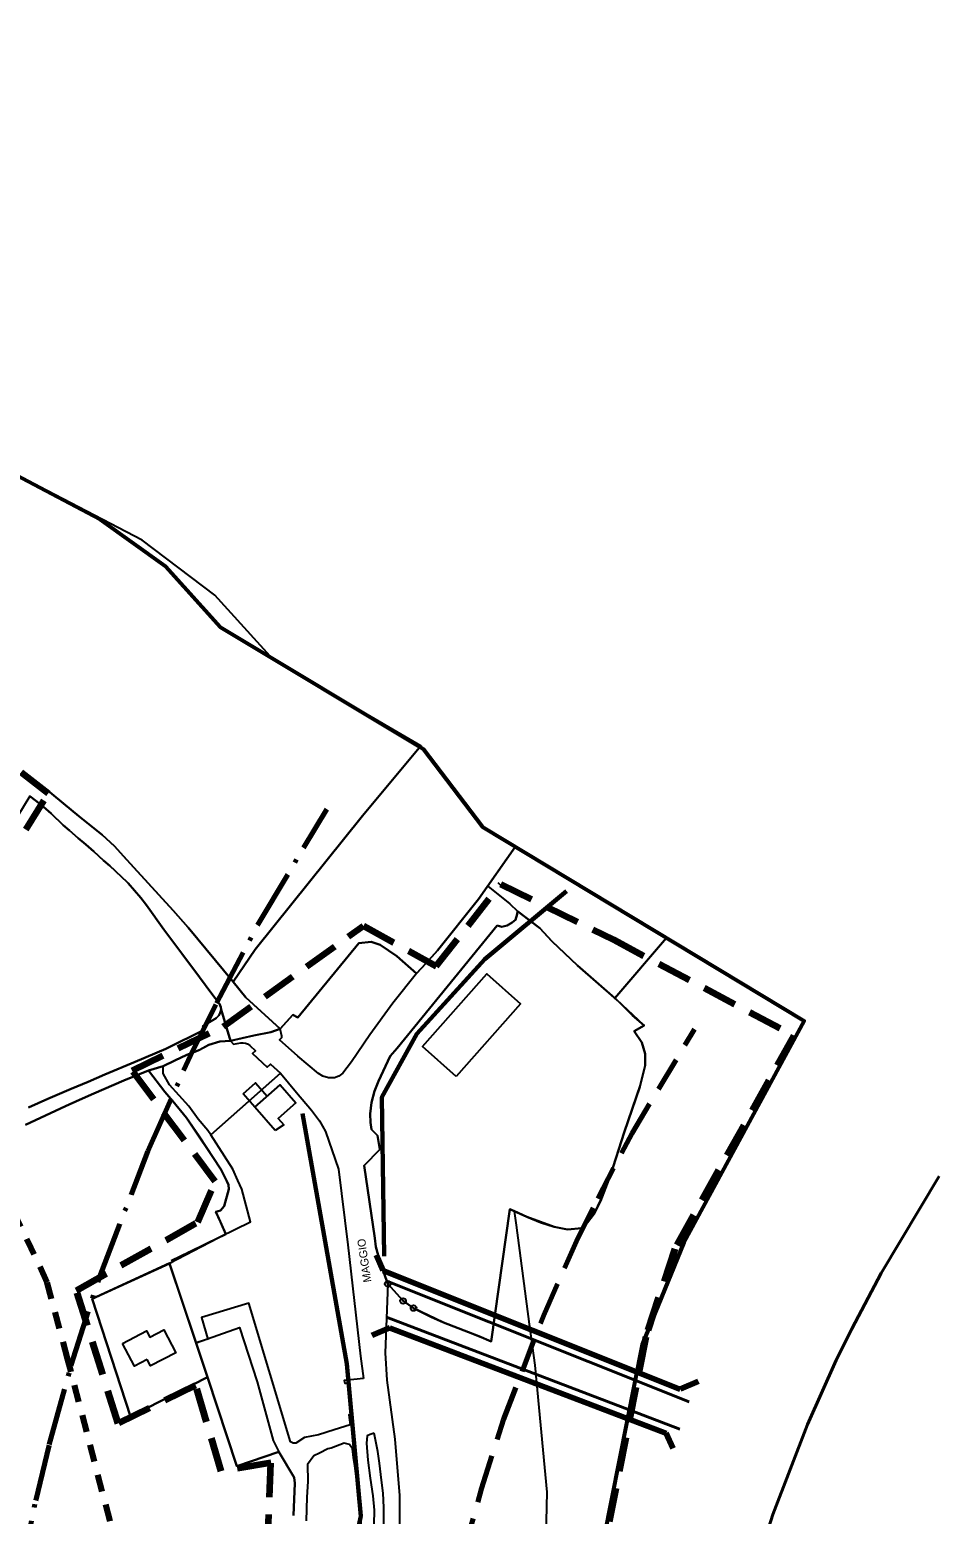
# Model space of a CAD drawing. Extents: x 654952 to 658955, y 890426 to 894481.
# Drawn here: x 658129 to 658448, y 893668 to 894188 of the extents above; entities that cross this region are included whole.
import ezdxf

# ---------------------------------------------------------------- set-up
doc = ezdxf.new("R2010")
doc.units = 0
doc.header["$LTSCALE"] = 4
doc.header["$PDMODE"] = 32
doc.header["$PDSIZE"] = 2
for name, pattern in [('DOT_DASHED', [7.7, 5, -1.2, 0.3, -1.2]), ('MEDIUM_DASHED', [4.5, 3, -1.5]), ('SHORT_DASHED', [2.7, 1.5, -1.2])]:
    doc.linetypes.add(name, pattern=pattern)
for name, color, linetype, lineweight in [('11', 7, 'Continuous', 25), ('14', 7, 'Continuous', 25), ('19', 7, 'Continuous', 25), ('21', 7, 'Continuous', 25), ('31', 7, 'Continuous', 25), ('40', 7, 'Continuous', 60), ('41', 7, 'SHORT_DASHED', 80), ('43', 7, 'Continuous', 25), ('45', 7, 'Continuous', 25), ('5', 7, 'Continuous', 25), ('55', 7, 'Continuous', 25), ('59', 7, 'Continuous', 53), ('6', 7, 'Continuous', 25), ('7', 7, 'MEDIUM_DASHED', 100), ('9', 7, 'Continuous', 25)]:
    doc.layers.add(name, color=color, linetype=linetype, lineweight=lineweight)
doc.layers.add('58', color=7, linetype='Continuous')

msp = doc.modelspace()

# ---------------------------------------------------------------- linework, layer by layer
at = {"layer": '11'}
msp.add_line((658187.79, 893727.98), (658178.45, 893755.87), dxfattribs=at)
for points in [[(658203.71, 893781.87), (658202.33, 893784.87), (658200.58, 893788.87), (658197.71, 893793.37), (658192.84, 893800.82), (658217.26, 893822.43), (658222.86, 893815.72), (658228.16, 893809.56)], [(658228.16, 893809.56), (658230.93, 893805.79), (658233.04, 893802.06), (658237.58, 893788.87), (658240.83, 893762.37), (658245.33, 893723.37), (658246.31, 893715.53)], [(658178.95, 893756.87), (658185.33, 893759.87), (658206.83, 893770.37), (658203.71, 893781.87)], [(658246.31, 893715.53), (658239.58, 893714.87), (658239.83, 893713.87), (658240.71, 893713.87), (658242.21, 893702.87), (658241.21, 893702.87), (658241.71, 893699.37), (658236.14, 893697.62), (658230.58, 893695.87), (658225.71, 893694.87), (658222.71, 893692.87), (658221.71, 893692.87), (658220.83, 893693.37), (658206.21, 893741.87), (658189.58, 893736.87), (658191.83, 893729.37), (658190.33, 893728.87), (658187.79, 893727.98)]]:
    msp.add_lwpolyline(points, dxfattribs=at)
at = {"layer": '14'}
for points in [[(658247.36, 893637.43), (658248.48, 893637.43), (658249.61, 893640.43), (658251.24, 893646.43), (658252.61, 893654.43), (658253.11, 893659.43), (658253.48, 893665.43), (658253.48, 893670.43), (658253.24, 893675.43), (658252.61, 893679.93), (658251.98, 893685.93), (658251.36, 893689.93), (658250.11, 893696.43)], [(658250.11, 893696.43), (658248.74, 893695.93), (658247.61, 893695.43), (658247.36, 893692.93), (658247.86, 893686.93), (658248.74, 893680.68), (658249.61, 893674.43), (658250.11, 893669.43), (658249.98, 893664.43)]]:
    msp.add_lwpolyline(points, dxfattribs=at)
at = {"layer": '19'}
msp.add_line((658217.26, 893822.43), (658192.84, 893800.82), dxfattribs=at)
for points in [[(658176.21, 893824.87), (658180.33, 893826.87), (658184.45, 893828.87), (658188.45, 893830.37), (658192.21, 893832.37), (658196, 893833.61), (658199.8, 893833.83), (658200.88, 893832.61), (658203.44, 893833.07), (658204.23, 893833.13), (658205.05, 893833), (658205.76, 893832.72), (658206.5, 893832.2), (658208.57, 893830.32), (658207.44, 893829.33), (658212.66, 893824.6), (658213.78, 893825.59), (658217.26, 893822.43)], [(658192.84, 893800.82), (658191.83, 893802.37), (658188.45, 893806.37), (658185.21, 893810.87), (658178.45, 893818.37), (658176.21, 893822.37), (658176.21, 893824.87)]]:
    msp.add_lwpolyline(points, dxfattribs=at)
at = {"layer": '21'}
msp.add_line((658260.21, 893742.69), (658263.9, 893740.19), dxfattribs=at)
for points in [[(658344.61, 893839.2), (658340.59, 893842.69), (658335.09, 893848.19), (658321.34, 893860.19), (658312.34, 893868.69), (658308.09, 893873.19), (658304.21, 893876.19), (658300.28, 893879.19), (658300.21, 893878.19)], [(658293.21, 893874.19), (658258.09, 893831.19), (658255.68, 893828.36)], [(658300.21, 893878.19), (658299.59, 893876.19), (658298.47, 893875.19), (658296.71, 893874.19), (658294.84, 893873.69), (658293.21, 893874.19)], [(658297.56, 893774.87), (658303.59, 893772.19), (658308.34, 893770.19), (658313.09, 893768.69), (658317.84, 893767.69), (658322.84, 893768.19), (658324.84, 893770.19), (658327.09, 893773.19), (658329.34, 893777.69), (658332.84, 893786.69), (658337.59, 893801.69), (658343.09, 893817.69), (658344.97, 893825.19), (658344.97, 893829.19), (658343.84, 893833.19), (658341.09, 893837.19), (658344.61, 893839.2)], [(658255.68, 893828.36), (658251.59, 893819.69), (658250.21, 893816.19), (658249.21, 893812.19), (658248.71, 893808.19), (658248.84, 893805.19), (658249.21, 893802.69), (658251.21, 893800.69), (658252.09, 893795.69), (658246.59, 893790.19)], [(658246.59, 893790.19), (658250.34, 893764.69), (658250.71, 893761.69), (658251.47, 893758.69), (658252.84, 893754.19), (658254.84, 893748.69)], [(658263.9, 893740.19), (658269.97, 893737.19), (658274.34, 893735.19), (658286.8, 893730.37), (658291.1, 893728.51), (658297.56, 893774.87)]]:
    msp.add_lwpolyline(points, dxfattribs=at)
for p in [(658254.84, 893748.69), (658260.21, 893742.69)]:
    msp.add_point(p, dxfattribs=at)
at = {"layer": '31'}
for points in [[(658129.01, 893810.44), (658135.82, 893813.44), (658144.01, 893816.94), (658149.89, 893819.44), (658155.76, 893821.94), (658166.45, 893826.44), (658177.13, 893830.94), (658190.76, 893837.7), (658190.14, 893838.96), (658194.74, 893841.75), (658194.74, 893841.75), (658195.72, 893842.63), (658196.17, 893843.6), (658196.47, 893844.7), (658196.39, 893845.6), (658195.95, 893846.7), (658193.28, 893850.28), (658188.89, 893856.1), (658182.69, 893864.32), (658176.46, 893872.78), (658170.35, 893881.27), (658168.34, 893883.85), (658166.2, 893886.44), (658163.89, 893888.94), (658163.31, 893889.54), (658161.88, 893890.95), (658159.38, 893893.29), (658157.47, 893895.05), (658155.34, 893896.98), (658151.88, 893900.06), (658149.07, 893902.52), (658146.48, 893904.76), (658143.44, 893907.39), (658141.15, 893909.35), (658137.01, 893913.44), (658134.26, 893915.69), (658131.51, 893917.94), (658129.47, 893919.47), (658118.76, 893901.94)], [(658196.47, 893844.7), (658196.17, 893843.6), (658195.72, 893842.63), (658194.74, 893841.75), (658194.74, 893841.75), (658190.14, 893838.96), (658190.76, 893837.7), (658177.13, 893830.94), (658166.45, 893826.44), (658155.76, 893821.94), (658149.89, 893819.44), (658144.01, 893816.94), (658135.82, 893813.44), (658129.01, 893810.44)], [(658192.21, 893832.37), (658196, 893833.61), (658199.8, 893833.83), (658196.47, 893844.7)], [(658176.21, 893824.87), (658180.33, 893826.87), (658184.45, 893828.87), (658188.45, 893830.37), (658192.21, 893832.37)], [(658221.89, 893667.62), (658222.32, 893678.87), (658222.07, 893680.87), (658216.69, 893689.87), (658201.95, 893684.87), (658191.7, 893715.97), (658164.71, 893702.26), (658151.33, 893743.44), (658178.45, 893755.87), (658185.32, 893759.87), (658198.15, 893766.13), (658196.26, 893770.37), (658194.69, 893773.87), (658196.32, 893774.37), (658197.57, 893775.87), (658199.19, 893781.87), (658199.07, 893783.37), (658197.76, 893786.12), (658196.45, 893788.87), (658188.76, 893800.37), (658184.32, 893806.87), (658179.64, 893812.62), (658176.82, 893815.87), (658171.07, 893823.37), (658162.45, 893819.87), (658151.95, 893815.37), (658146.95, 893813.12), (658141.95, 893810.87), (658134.95, 893807.62), (658127.95, 893804.37)], [(658134.95, 893807.62), (658141.95, 893810.87), (658146.95, 893813.12), (658151.95, 893815.37), (658162.45, 893819.87), (658171.07, 893823.37), (658176.21, 893824.87)], [(658127.95, 893804.37), (658134.95, 893807.62)]]:
    msp.add_lwpolyline(points, dxfattribs=at)
at = {"layer": '40'}
for points in [[(658317.48, 893886.17), (658288.82, 893862.41), (658265.07, 893836.19), (658252.79, 893814.07), (658253.61, 893758.35)], [(658224.95, 893808.33), (658240.51, 893720.65), (658245.42, 893667.39), (658238.05, 893634.61)]]:
    msp.add_lwpolyline(points, dxfattribs=at)
at = {"layer": '41', "linetype": 'Continuous'}
for p, q in [((658253.29, 893753.36), (658250.89, 893758.72)), ((658253.29, 893753.36), (658357.26, 893711.84)), ((658255.62, 893733.31), (658249.3, 893730.6)), ((658255.62, 893733.31), (658352.36, 893696.42)), ((658363.58, 893714.55), (658357.26, 893711.84)), ((658354.76, 893691.07), (658352.36, 893696.42))]:
    msp.add_line(p, q, dxfattribs=at)
at = {"layer": '41', "linetype": 'Continuous', "lineweight": 40}
for p, q in [((658254.87, 893749.5), (658360.41, 893707.35)), ((658254.41, 893736.98), (658357.08, 893697.83))]:
    msp.add_line(p, q, dxfattribs=at)
at = {"layer": '41'}
msp.add_lwpolyline([(658163.03, 893644.67), (658142.74, 893722.59), (658135.58, 893749.15)], dxfattribs=at)
msp.add_arc((657304.29, 893371.06), 913.24, 24.45688, 31.0983, dxfattribs=at)
at = {"layer": '43'}
msp.add_line((658334.42, 893848.77), (658352.42, 893869.89), dxfattribs=at)
for points in [[(658266.41, 893937.09), (658214.83, 893967.25), (658194.33, 893989.87), (658168.89, 894009.06), (658121.55, 894033.74), (658121.55, 894033.74), (658085.51, 894058.42), (658016.08, 894099.23), (658016.08, 894099.23), (657987.82, 894112.94), (657939.76, 894138.3), (657874.04, 894162.29), (657811.4, 894192.37), (657779.35, 894208.91), (657757.45, 894224.67), (657703.03, 894250.03), (657703.03, 894250.03), (657646.5, 894254.15)], [(658266.41, 893937.09), (658246.01, 893912.55), (658208.44, 893865.75), (658200.67, 893854.4), (658205.11, 893849), (658217.13, 893837.94)], [(658200.67, 893854.4), (658208.44, 893865.75), (658246.01, 893912.55), (658266.41, 893937.09)], [(658264.97, 893857.41), (658268.24, 893860.92), (658272.26, 893865.44), (658286.63, 893883.44), (658299.53, 893901.82), (658288.06, 893908.75), (658266.41, 893937.09)], [(658126.76, 893927.94), (658135.26, 893921.94)], [(658135.26, 893921.94), (658146.63, 893912.44), (658154.88, 893905.94), (658159.13, 893901.94), (658162.26, 893898.44), (658165.88, 893894.44), (658179.76, 893879.44), (658185.01, 893873.44), (658200.67, 893854.4)], [(658352.42, 893869.89), (658299.53, 893901.82), (658289.89, 893887.98), (658297.6, 893881.73), (658300.28, 893879.19)], [(658300.28, 893879.19), (658308.09, 893873.19), (658312.34, 893868.69), (658321.34, 893860.19), (658334.42, 893848.77)], [(658217.13, 893837.94), (658221.63, 893842.94), (658223.38, 893841.94), (658244.75, 893867.94), (658249, 893868.44), (658252.25, 893867.44), (658258, 893863.44), (658264.97, 893857.41)], [(658352.42, 893869.89), (658400.68, 893840.76), (658358.48, 893763.16), (658343.9, 893727.46), (658322.5, 893619.12), (658323.74, 893553.3), (658329.32, 893488.12), (658329.63, 893434.42), (658307.02, 893435.52), (658306.12, 893451.76), (658304.87, 893451.7), (658305, 893471.76), (658303.62, 893485.76), (658302.62, 893492.76), (658303.75, 893498.26), (658303.12, 893504.76), (658296.25, 893520.26), (658292, 893524.26), (658287.7, 893525.94), (658282.87, 893527.26), (658268.47, 893525.98)], [(658299.21, 893774.15), (658308.34, 893770.19), (658313.09, 893768.69), (658317.84, 893767.69), (658322.84, 893768.19), (658324.84, 893770.19), (658327.09, 893773.19), (658329.61, 893778.34), (658333.11, 893787.34), (658337.59, 893801.69), (658343.36, 893818.34), (658344.97, 893825.19), (658344.97, 893829.19), (658343.84, 893833.19), (658341.09, 893837.19), (658344.61, 893839.2), (658335.09, 893848.19), (658334.42, 893848.77), (658352.42, 893869.89)], [(658299.21, 893774.15), (658297.56, 893774.87), (658291.1, 893728.51), (658274.34, 893735.19), (658263.9, 893740.19), (658260.21, 893742.69), (658254.84, 893748.69), (658253.95, 893724.56), (658254.58, 893715.01), (658257.34, 893694.32), (658258.94, 893674.6), (658258.94, 893654.62)], [(658268.47, 893525.98), (658268.49, 893526.23), (658271.18, 893536.99), (658279.37, 893558.7), (658292.56, 893589.24), (658299.92, 893607.65), (658309.97, 893645.31), (658310.68, 893675.74), (658306.42, 893720.25), (658304.44, 893734.6), (658299.92, 893769.26), (658299.21, 893774.15)], [(658268.47, 893525.98), (658268.49, 893526.23), (658271.18, 893536.99), (658279.37, 893558.7), (658292.56, 893589.24), (658299.92, 893607.65), (658309.97, 893645.31), (658310.68, 893675.74), (658306.42, 893720.25), (658304.44, 893734.6), (658299.92, 893769.26), (658299.21, 893774.15)]]:
    msp.add_lwpolyline(points, dxfattribs=at)
at = {"layer": '45', "linetype": 'DOT_DASHED', "lineweight": 70}
msp.add_lwpolyline([(657888.75, 892244.36), (657949.53, 892498.78), (657993.28, 892680.38), (658112.95, 893179.41), (658123.49, 893235.71), (658127.84, 893290.79), (658125.12, 893359.25), (658122.7, 893382.9), (658114.35, 893470.93), (658113.32, 893505.97), (658113.89, 893537.78), (658115.35, 893563.44), (658117.94, 893594.58), (658121.29, 893618.7), (658125.97, 893646.13), (658131.56, 893672.78), (658136.29, 893692.48), (658143.9, 893719.95), (658153.86, 893751.08), (658170.87, 893795.19), (658185.72, 893828.64), (658194.88, 893846.97), (658209.57, 893874.93), (658233.56, 893914.96)], dxfattribs=at)
at = {"layer": '45', "linetype": 'MEDIUM_DASHED', "lineweight": 70}
msp.add_lwpolyline([(658035.6, 892213.52), (658095.39, 892463.77), (658139.14, 892645.31), (658259.68, 893148.09), (658272.39, 893215.94), (658278.08, 893287.85), (658274.82, 893369.87), (658271.98, 893397.63), (658264.14, 893480.23), (658263.35, 893506.84), (658263.8, 893532.17), (658264.99, 893552.95), (658267.07, 893578), (658269.55, 893595.75), (658273.36, 893618.11), (658277.93, 893639.87), (658281.55, 893654.95), (658287.66, 893677.05), (658295.4, 893701.19), (658309.47, 893737.74), (658321.42, 893764.63), (658328.38, 893778.55), (658340.4, 893801.43), (658362.23, 893837.86)], dxfattribs=at)
at = {"layer": '45', "lineweight": 40}
msp.add_lwpolyline([(658133.5, 892192.94), (658192.63, 892440.44), (658236.37, 892621.94), (658357.51, 893127.22), (658371.66, 893202.76), (658378.23, 893285.88), (658374.62, 893376.94), (658371.5, 893407.44), (658364, 893486.44), (658363.38, 893507.44), (658363.75, 893528.44), (658364.75, 893545.94), (658366.5, 893566.94), (658368.38, 893580.44), (658371.62, 893599.44), (658375.5, 893617.94), (658378.38, 893629.94), (658383.5, 893648.44), (658389.75, 893667.94), (658401.88, 893699.44), (658411.88, 893721.94), (658417.38, 893732.94), (658427.62, 893752.44), (658448, 893786.44)], dxfattribs=at)
at = {"layer": '5'}
for points in [[(658179.76, 893879.44), (658165.88, 893894.44), (658162.26, 893898.44), (658159.13, 893901.94), (658154.88, 893905.94), (658146.63, 893912.44), (658135.26, 893921.94), (658126.76, 893927.94)], [(658129.47, 893919.47), (658131.51, 893917.94), (658134.26, 893915.69), (658137.01, 893913.44), (658141.15, 893909.35), (658143.44, 893907.39), (658146.48, 893904.76), (658149.07, 893902.52), (658151.88, 893900.06), (658155.34, 893896.98), (658157.47, 893895.05), (658159.38, 893893.29), (658161.88, 893890.95), (658163.31, 893889.54), (658163.89, 893888.94), (658166.2, 893886.44), (658168.34, 893883.85), (658170.35, 893881.27), (658176.46, 893872.78), (658182.69, 893864.32), (658188.89, 893856.1), (658193.28, 893850.28), (658195.95, 893846.7), (658196.39, 893845.6), (658196.47, 893844.7), (658199.8, 893833.83)], [(658199.8, 893833.83), (658208.01, 893835.66), (658213.92, 893836.81), (658217.13, 893837.94), (658205.11, 893849), (658200.67, 893854.4), (658185.01, 893873.44), (658179.76, 893879.44)]]:
    msp.add_lwpolyline(points, dxfattribs=at)
at = {"layer": '55'}
for p, q in [((658260.21, 893742.69), (658254.84, 893748.69)), ((658263.9, 893740.19), (658260.21, 893742.69))]:
    msp.add_line(p, q, dxfattribs=at)
for points in [[(658299.53, 893901.82), (658286.63, 893883.44), (658272.26, 893865.44), (658268.24, 893860.92), (658264.97, 893857.41)], [(658300.28, 893879.19), (658308.09, 893873.19), (658312.34, 893868.69), (658321.34, 893860.19), (658334.42, 893848.77), (658352.42, 893869.89), (658299.53, 893901.82)], [(658293.21, 893874.19), (658294.84, 893873.69), (658296.71, 893874.19), (658298.47, 893875.19), (658299.59, 893876.19), (658300.21, 893878.19), (658300.28, 893879.19)], [(658255.68, 893828.36), (658258.09, 893831.19), (658293.21, 893874.19)], [(658264.97, 893857.41), (658258, 893863.44), (658252.25, 893867.44), (658249, 893868.44), (658244.75, 893867.94), (658223.38, 893841.94), (658221.63, 893842.94), (658217.13, 893837.94), (658213.92, 893836.81), (658208.01, 893835.66)], [(658381.79, 893852.16), (658352.42, 893869.89), (658334.42, 893848.77), (658338.32, 893845.01), (658340.59, 893842.69), (658344.61, 893839.2), (658341.09, 893837.19), (658343.84, 893833.19), (658344.97, 893829.19), (658344.97, 893825.19), (658343.09, 893817.69), (658343.09, 893817.69), (658337.59, 893801.69), (658332.84, 893786.69), (658329.34, 893777.69), (658327.09, 893773.19), (658324.84, 893770.19), (658322.84, 893768.19)], [(658040.09, 892492.62), (658056.01, 892512.42), (658077.73, 892541.6), (658117.44, 892608.97), (658146.29, 892663.3), (658176.86, 892798.67), (658197.47, 892851.1), (658213.6, 892873.76), (658238.11, 892899.22), (658275.65, 893091.38), (658324.67, 893198.8), (658324.98, 893205.94), (658316.81, 893217.01), (658315.67, 893225.5), (658324.05, 893218.98), (658327.46, 893312.74), (658329.63, 893434.42), (658329.32, 893488.12), (658323.74, 893553.3), (658322.5, 893619.12), (658343.9, 893727.46), (658358.49, 893763.16), (658400.68, 893840.75), (658381.79, 893852.16)], [(658208.01, 893835.66), (658199.8, 893833.83), (658196, 893833.61), (658192.21, 893832.37), (658189.07, 893830.6), (658184.45, 893828.87), (658180.33, 893826.87), (658176.21, 893824.87), (658171.07, 893823.37), (658176.82, 893815.87), (658179.64, 893812.62), (658184.32, 893806.87), (658196.45, 893788.87), (658199.07, 893783.37), (658199.19, 893781.87), (658197.57, 893775.87), (658196.32, 893774.37), (658194.69, 893773.87), (658198.15, 893766.13), (658178.45, 893755.87), (658191.7, 893715.97), (658201.95, 893684.87), (658216.71, 893689.87), (658222.07, 893680.87), (658222.32, 893678.87), (658221.89, 893667.62)], [(658251.21, 893800.69), (658249.21, 893802.69), (658248.84, 893805.19), (658248.71, 893808.19), (658249.21, 893812.19), (658250.21, 893816.19), (658251.59, 893819.69), (658255.68, 893828.36)], [(658254.84, 893748.69), (658252.84, 893754.19), (658251.47, 893758.69), (658250.71, 893761.69), (658250.34, 893764.69), (658246.59, 893790.19), (658252.09, 893795.69), (658251.21, 893800.69)], [(658322.84, 893768.19), (658317.84, 893767.69), (658313.09, 893768.69), (658303.59, 893772.19), (658299.21, 893774.15), (658297.56, 893774.87), (658291.1, 893728.51), (658286.8, 893730.37), (658274.34, 893735.19), (658263.9, 893740.19)]]:
    msp.add_lwpolyline(points, dxfattribs=at)
for p in [(658254.84, 893748.69), (658260.21, 893742.69), (658263.9, 893740.19)]:
    msp.add_point(p, dxfattribs=at)
at = {"layer": '59'}
msp.add_lwpolyline([(658033.37, 894087.55), (658074.01, 894063.03), (658105.65, 894041.92), (658154.04, 894016.47), (658177, 894000.01), (658196.24, 893978.59), (658267.28, 893936.06), (658288.06, 893908.75), (658400.68, 893840.75), (658358.49, 893763.16), (658343.9, 893727.46), (658322.5, 893619.12)], dxfattribs=at)
at = {"layer": '6'}
for points in [[(658278.83, 893821.34), (658267.06, 893831.77), (658289.6, 893857.22), (658301.37, 893846.8)], [(658204.18, 893815.21), (658208.54, 893819.03), (658212.63, 893814.38), (658208.27, 893810.55)], [(658215.4, 893802.44), (658208.27, 893810.55), (658217.14, 893818.34), (658222.68, 893812.03), (658216.52, 893806.62), (658218.5, 893804.36)]]:
    msp.add_lwpolyline(points, close=True, dxfattribs=at)
for points in [[(658161.97, 893727.85), (658170.4, 893732.24), (658171.56, 893730.02), (658176.43, 893732.56), (658180.59, 893724.58), (658171.72, 893719.96), (658170.57, 893722.18)], [(658170.57, 893722.18), (658166.13, 893719.87), (658161.97, 893727.85)]]:
    msp.add_lwpolyline(points, dxfattribs=at)
at = {"layer": '7'}
for points in [[(658118.53, 893892.48), (658135.93, 893920.34), (658035, 893999.74)], [(658118.53, 893892.48), (658135.93, 893920.34), (658035, 893999.74)], [(658271.86, 893859.9), (658294.4, 893888.67), (658333.87, 893869.22), (658397.09, 893835.57), (658355.34, 893760.97), (658345.21, 893730.15), (658324.56, 893626.35)], [(658212.72, 893655.96), (658213.93, 893685.96), (658196.51, 893683.12), (658187.58, 893713.13), (658160.44, 893699.75), (658145.85, 893746.38), (658188.4, 893770.3), (658194.47, 893784.48), (658165.29, 893823.41), (658197.31, 893838.81), (658246.34, 893874.09), (658271.86, 893859.9)]]:
    msp.add_lwpolyline(points, dxfattribs=at)
at = {"layer": '9'}
for points in [[(658223.35, 893828.4), (658216.98, 893834.14), (658217.75, 893834.94), (658217.75, 893835.44), (658217.13, 893837.94), (658221.63, 893842.94), (658223.37, 893841.94), (658244.75, 893867.94), (658249, 893868.44), (658252.25, 893867.44), (658258, 893863.44), (658264.97, 893857.41)], [(658264.97, 893857.41), (658256.63, 893846.94), (658248.63, 893835.94), (658242.13, 893826.44), (658239.16, 893822.52), (658237.76, 893821.46), (658236.17, 893820.88), (658234.1, 893820.78), (658232.12, 893821.41), (658230.59, 893822.29), (658230.59, 893822.29), (658223.35, 893828.4)], [(658187.79, 893727.98), (658202.95, 893733.37), (658209.08, 893714.37), (658211.89, 893704.12), (658214.71, 893693.87), (658216.71, 893689.87)], [(658216.71, 893689.87), (658201.95, 893684.87), (658191.7, 893715.97), (658187.79, 893727.98)], [(658245.86, 893660.94), (658245.12, 893669.94), (658244.74, 893673.94), (658243.36, 893684.94), (658242.86, 893687.94), (658242.49, 893690.94), (658241.49, 893692.44), (658239.62, 893692.94), (658234.99, 893691.19), (658233.86, 893690.94), (658230.99, 893689.44), (658228.99, 893688.44), (658226.74, 893685.44), (658226.86, 893679.44), (658226.49, 893673.94), (658226.3, 893665.69)]]:
    msp.add_lwpolyline(points, dxfattribs=at)
msp.add_lwpolyline([(658191.7, 893715.97), (658178.38, 893755.94), (658151.33, 893743.44), (658164.71, 893702.26)], close=True, dxfattribs=at)

# ---------------------------------------------------------------- texts
at = {"layer": '58'}
msp.add_text('MAGGIO', height=2.802, rotation=98.254, dxfattribs=at).set_placement((658249.11, 893749.43))

doc.saveas('drawing.dxf')
